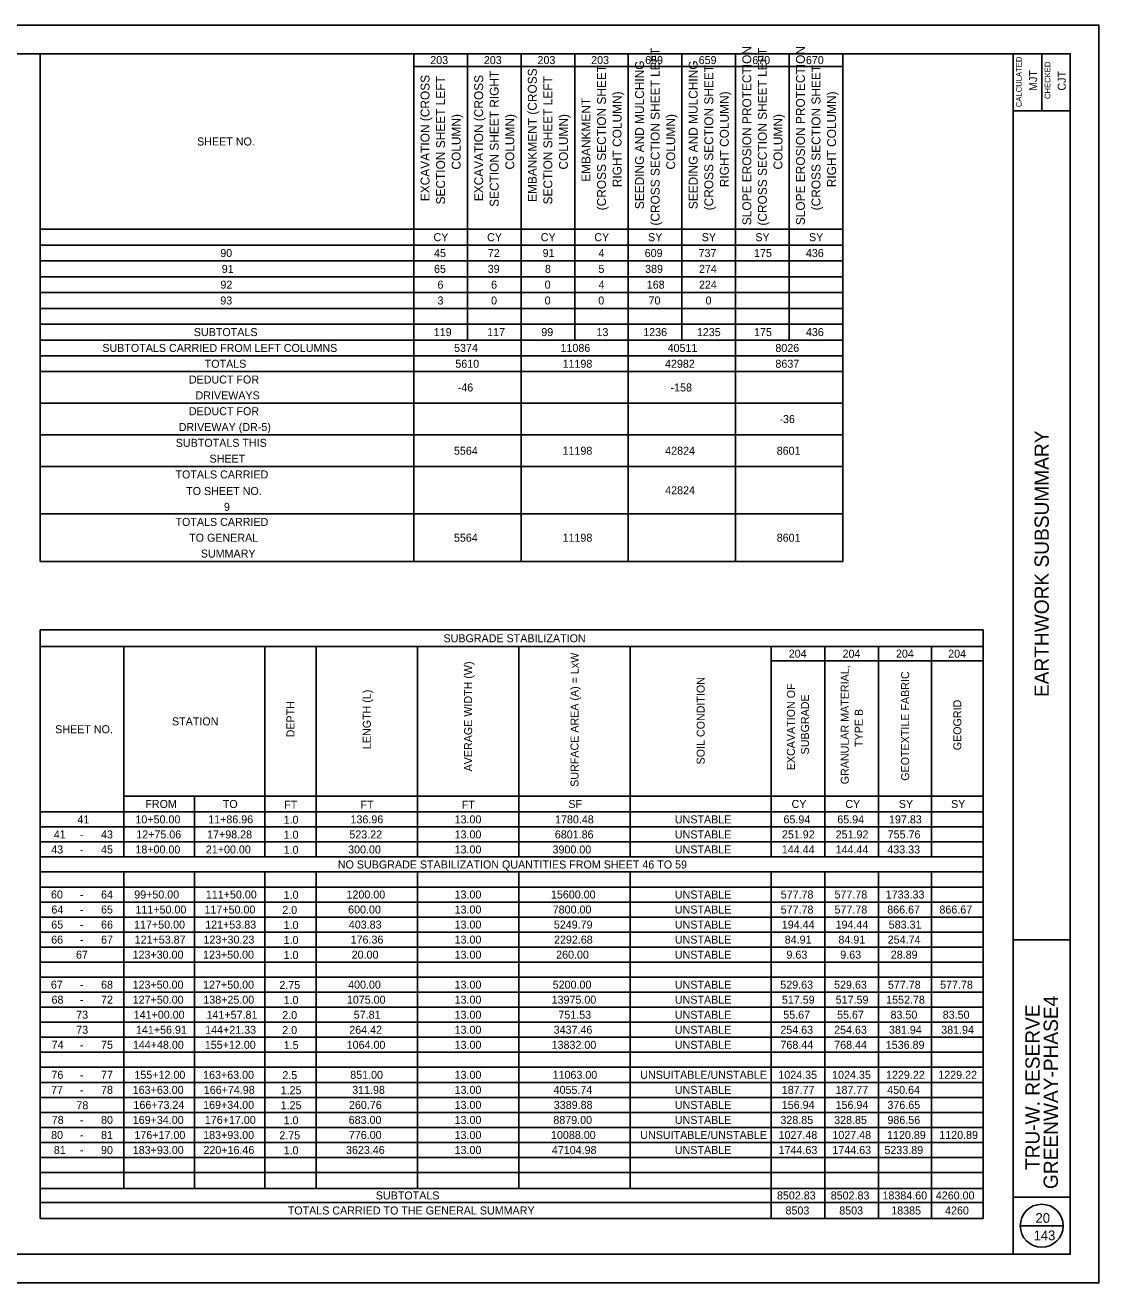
# Model space of a CAD drawing. Extents: x -16 to 102, y -13 to 9.
# Drawn here: x -1.15 to 17.63, y -12.91 to 9.09 of the extents above; entities that cross this region are included whole.
import ezdxf

# ---------------------------------------------------------------- set-up
doc = ezdxf.new("R2010")
doc.units = 0
for name, color, linetype in [('PV_P_EOP', 7, 'Continuous'), ('SH_Border', 7, 'Continuous'), ('SH_Cut_Line', 7, 'Continuous'), ('SH_Data', 7, 'Continuous'), ('TX_P_1', 7, 'Continuous')]:
    doc.layers.add(name, color=color, linetype=linetype)

msp = doc.modelspace()

# ---------------------------------------------------------------- linework, layer by layer
at = {"layer": 'SH_Border'}
for p, q in [((16.129, -12.407), (16.129, 8.593)), ((16.629, 8.593), (16.629, 7.593)), ((16.129, 7.593), (17.129, 7.593)), ((16.129, -6.907), (17.129, -6.907)), ((16.129, -11.407), (17.129, -11.407))]:
    msp.add_line(p, q, dxfattribs=at)
msp.add_lwpolyline([(-14.371, 8.593), (17.129, 8.593), (17.129, -12.407), (-14.371, -12.407)], close=True, dxfattribs=at)
at = {"layer": 'SH_Cut_Line'}
msp.add_lwpolyline([(-16.371, -12.907), (17.629, -12.907), (17.629, 9.093), (-16.371, 9.093)], close=True, dxfattribs=at)
at = {"layer": 'SH_Data'}
for p, q in [((-0.886, 8.593), (13.151, 8.593)), ((-0.886, 8.593), (-0.886, -0.288)), ((5.648, 8.593), (5.648, -0.288)), ((6.586, 8.593), (6.586, 3.585)), ((7.524, 8.593), (7.524, -0.288)), ((8.462, 8.593), (8.462, 3.585)), ((9.4, 8.593), (9.4, -0.288)), ((10.338, 8.593), (10.338, 3.585)), ((11.276, 8.593), (11.276, -0.288)), ((12.214, 8.593), (12.214, 3.585)), ((13.151, 8.593), (13.151, -0.288)), ((5.648, 8.372), (13.151, 8.372)), ((-0.886, 5.522), (13.151, 5.522)), ((-0.886, 5.245), (13.151, 5.245)), ((-0.886, 4.969), (13.151, 4.969)), ((-0.886, 4.692), (13.151, 4.692)), ((-0.886, 4.415), (13.151, 4.415)), ((-0.886, 4.139), (13.151, 4.139)), ((-0.886, 3.862), (13.151, 3.862)), ((-0.886, 3.585), (13.151, 3.585)), ((-0.886, 3.309), (13.151, 3.309)), ((-0.886, 3.032), (13.151, 3.032)), ((-0.886, 2.479), (13.151, 2.479)), ((-0.886, 1.925), (13.151, 1.925)), ((-0.886, 1.372), (13.151, 1.372)), ((-0.886, 0.542), (13.151, 0.542)), ((-0.886, -0.288), (13.151, -0.288)), ((-0.886, -1.487), (15.604, -1.487)), ((-0.886, -1.487), (-0.886, -11.779)), ((15.604, -1.487), (15.604, -11.779)), ((-0.886, -1.777), (15.604, -1.777)), ((0.58, -1.777), (0.58, -5.457)), ((3.043, -1.777), (3.043, -5.457)), ((3.942, -1.777), (3.942, -5.457)), ((5.713, -1.777), (5.713, -5.457)), ((7.483, -1.777), (7.483, -5.457)), ((9.434, -1.777), (9.434, -5.457)), ((11.896, -1.777), (11.896, -5.457)), ((12.837, -1.777), (12.837, -5.457)), ((13.778, -1.777), (13.778, -5.457)), ((14.705, -1.777), (14.705, -5.457)), ((11.896, -2.026), (15.604, -2.026)), ((0.58, -4.392), (15.604, -4.392)), ((1.812, -4.392), (1.812, -5.457)), ((-0.886, -4.669), (15.604, -4.669)), ((-0.886, -4.932), (15.604, -4.932)), ((-0.886, -5.194), (15.604, -5.194)), ((-0.886, -5.457), (15.604, -5.457)), ((-0.886, -5.72), (15.604, -5.72)), ((0.58, -5.72), (0.58, -11.254)), ((1.812, -5.72), (1.812, -11.254)), ((3.043, -5.72), (3.043, -11.254)), ((3.942, -5.72), (3.942, -11.254)), ((5.713, -5.72), (5.713, -11.254)), ((7.483, -5.72), (7.483, -11.254)), ((9.434, -5.72), (9.434, -11.254)), ((11.896, -5.72), (11.896, -11.779)), ((12.837, -5.72), (12.837, -11.779)), ((13.778, -5.72), (13.778, -11.779)), ((14.705, -5.72), (14.705, -11.779)), ((-0.886, -5.983), (15.604, -5.983)), ((-0.886, -6.246), (15.604, -6.246)), ((-0.886, -6.509), (15.604, -6.509)), ((-0.886, -6.771), (15.604, -6.771)), ((-0.886, -7.034), (15.604, -7.034)), ((-0.886, -7.297), (15.604, -7.297)), ((-0.886, -7.56), (15.604, -7.56)), ((-0.886, -7.823), (15.604, -7.823)), ((-0.886, -8.086), (15.604, -8.086)), ((-0.886, -8.348), (15.604, -8.348)), ((-0.886, -8.611), (15.604, -8.611)), ((-0.886, -8.874), (15.604, -8.874)), ((-0.886, -9.137), (15.604, -9.137)), ((-0.886, -9.4), (15.604, -9.4)), ((-0.886, -9.663), (15.604, -9.663)), ((-0.886, -9.926), (15.604, -9.926)), ((-0.886, -10.188), (15.604, -10.188)), ((-0.886, -10.451), (15.604, -10.451)), ((-0.886, -10.714), (15.604, -10.714)), ((-0.886, -10.977), (15.604, -10.977)), ((-0.886, -11.254), (15.604, -11.254)), ((-0.886, -11.503), (15.604, -11.503)), ((-0.886, -11.779), (15.604, -11.779)), ((16.254, -11.907), (17.004, -11.907))]:
    msp.add_line(p, q, dxfattribs=at)
msp.add_circle((16.629, -11.907), 0.375, dxfattribs=at)

# ---------------------------------------------------------------- texts
at = {"layer": 'PV_P_EOP'}
for s, p in [('SHEET NO.', (1.859, 6.988)), ('SUBTOTALS', (1.802, 3.654)), ('SUBTOTALS CARRIED FROM LEFT COLUMNS', (0.202, 3.377)), ('TOTALS', (1.992, 3.1)), ('DEDUCT FOR ', (1.715, 2.824)), ('DRIVEWAYS', (1.831, 2.547)), ('DEDUCT FOR ', (1.715, 2.27)), ('DRIVEWAY (DR-5)', (1.537, 1.994)), ('SUBTOTALS THIS ', (1.486, 1.717)), ('SHEET', (2.077, 1.44)), ('TOTALS CARRIED ', (1.481, 1.164)), (' TO SHEET NO.', (1.616, 0.874)), ('9', (2.328, 0.597)), ('TOTALS CARRIED ', (1.481, 0.333)), (' TO GENERAL ', (1.668, 0.057)), ('SUMMARY', (1.924, -0.22)), ('SUBGRADE STABILIZATION', (6.168, -1.702)), ('STATION', (1.42, -3.155)), ('SHEET NO.', (-0.623, -3.293)), ('FROM', (0.954, -4.6)), ('TO', (2.309, -4.6)), ('SUBTOTALS', (4.984, -11.448)), ('TOTALS CARRIED TO THE GENERAL SUMMARY', (3.444, -11.711))]:
    msp.add_text(s, height=0.14, dxfattribs=at).set_placement(p)
for s, p in [('SURFACE AREA (A) = LxW', (8.529, -4.23)), ('AVERAGE WIDTH (W)', (6.668, -3.961)), ('SOIL CONDITION', (10.735, -3.839)), ('LENGTH (L)', (4.897, -3.57)), ('DEPTH', (3.562, -3.365))]:
    msp.add_text(s, height=0.14, rotation=90, dxfattribs=at).set_placement(p)
at = {"layer": 'SH_Data'}
for s, height, p in [('CALCULATED', 0.1, (16.281, 7.658)), ('CHECKED', 0.1, (16.781, 7.801)), ('MJT', 0.14, (16.549, 7.942)), ('CJT', 0.14, (17.049, 7.949)), ('EARTHWORK SUBSUMMARY', 0.25, (16.754, -2.66)), ('GREENWAY-PHASE4', 0.25, (16.913, -11.266)), ('TRU-W. RESERVE', 0.25, (16.594, -10.934))]:
    msp.add_text(s, height=height, rotation=90, dxfattribs=at).set_placement(p)
for s, p in [('20', (16.521, -11.857)), ('143', (16.488, -12.162))]:
    msp.add_text(s, height=0.17, dxfattribs=at).set_placement(p)
at = {"layer": 'TX_P_1'}
for s, height, p in [('(CROSS SECTION SHEET LEFT', 0.1556, (9.947, 5.587)), ('SLOPE EROSION PROTECTION', 0.1556, (11.55, 5.594)), ('(CROSS SECTION SHEET LEFT', 0.1556, (11.822, 5.587)), ('SLOPE EROSION PROTECTION', 0.1556, (12.488, 5.594)), ('(CROSS SECTION SHEET', 0.1556, (9.009, 5.854)), ('SEEDING AND MULCHING', 0.1556, (9.674, 5.874)), ('SEEDING AND MULCHING', 0.1556, (10.612, 5.874)), ('(CROSS SECTION SHEET', 0.1556, (10.885, 5.854)), ('(CROSS SECTION SHEET', 0.1556, (12.76, 5.854)), ('EXCAVATION (CROSS', 0.1556, (5.923, 6.014)), ('SECTION SHEET LEFT', 0.1556, (6.195, 5.957)), ('EXCAVATION (CROSS', 0.1556, (6.861, 6.014)), ('SECTION SHEET RIGHT', 0.1556, (7.133, 5.914)), ('EMBANKMENT (CROSS', 0.1556, (7.799, 6.001)), ('SECTION SHEET LEFT', 0.1556, (8.071, 5.957)), ('RIGHT COLUMN)', 0.1556, (9.281, 6.258)), ('RIGHT COLUMN)', 0.1556, (11.157, 6.258)), ('RIGHT COLUMN)', 0.1556, (13.033, 6.258)), ('EMBANKMENT', 0.1556, (8.737, 6.353)), ('COLUMN)', 0.1556, (6.467, 6.567)), ('COLUMN)', 0.1556, (7.405, 6.567)), ('COLUMN)', 0.1556, (8.343, 6.567)), ('COLUMN)', 0.1556, (10.219, 6.567)), ('COLUMN)', 0.1556, (12.095, 6.567)), ('GRANULAR MATERIAL,', 0.14, (13.255, -4.186)), ('GEOTEXTILE FABRIC', 0.14, (14.311, -4.124)), ('EXCAVATION OF', 0.14, (12.314, -3.941)), ('SUBGRADE', 0.14, (12.559, -3.664)), ('GEOGRID', 0.14, (15.224, -3.591)), ('TYPE B', 0.14, (13.5, -3.533))]:
    msp.add_text(s, height=height, rotation=90, dxfattribs=at).set_placement(p)
for s, p in [('203', (5.937, 8.412)), ('203', (6.874, 8.412)), ('203', (7.812, 8.412)), ('203', (8.75, 8.412)), ('659', (9.694, 8.412)), ('659', (10.631, 8.412)), ('670', (11.568, 8.412)), ('670', (12.506, 8.412)), ('CY', (5.993, 5.314)), ('CY', (6.931, 5.314)), ('CY', (7.869, 5.314)), ('CY', (8.806, 5.314)), ('SY', (9.746, 5.314)), ('SY', (10.684, 5.314)), ('SY', (11.622, 5.314)), ('SY', (12.56, 5.314)), ('90', (2.264, 5.037)), ('45', (6.003, 5.037)), ('72', (6.943, 5.037)), ('91', (7.902, 5.037)), ('4', (8.879, 5.037)), ('609', (9.687, 5.037)), ('737', (10.629, 5.037)), ('175', (11.599, 5.037)), ('436', (12.506, 5.037)), ('91', (2.29, 4.76)), ('65', (6.002, 4.76)), ('39', (6.941, 4.76)), ('8', (7.942, 4.76)), ('5', (8.878, 4.76)), ('389', (9.694, 4.76)), ('274', (10.636, 4.76)), ('92', (2.267, 4.484)), ('6', (6.063, 4.484)), ('6', (7.001, 4.484)), ('0', (7.937, 4.484)), ('4', (8.879, 4.484)), ('168', (9.723, 4.484)), ('224', (10.636, 4.484)), ('93', (2.265, 4.207)), ('3', (6.063, 4.207)), ('0', (7, 4.207)), ('0', (7.937, 4.207)), ('0', (8.875, 4.207)), ('70', (9.754, 4.207)), ('0', (10.751, 4.207)), ('119', (5.998, 3.654)), ('117', (6.932, 3.654)), ('99', (7.878, 3.654)), ('13', (8.844, 3.654)), ('1236', (9.661, 3.654)), ('1235', (10.599, 3.654)), ('175', (11.599, 3.654)), ('436', (12.506, 3.654)), ('5374', (6.353, 3.377)), ('11086', (8.214, 3.377)), ('40511', (10.087, 3.377)), ('8026', (11.972, 3.377)), ('5610', (6.375, 3.1)), ('11198', (8.25, 3.1)), ('42982', (10.042, 3.1)), ('8637', (11.973, 3.1)), ('-46', (6.417, 2.685)), ('-158', (10.139, 2.685)), ('-36', (12.043, 2.132)), ('5564', (6.351, 1.579)), ('11198', (8.25, 1.579)), ('42824', (10.045, 1.579)), ('8601', (11.995, 1.579)), ('42824', (10.045, 0.887)), ('5564', (6.351, 0.057)), ('11198', (8.25, 0.057)), ('8601', (11.995, 0.057)), ('204', (12.206, -1.971)), ('204', (13.147, -1.971)), ('204', (14.081, -1.971)), ('204', (14.994, -1.971)), ('FT', (3.382, -4.613)), ('FT', (4.717, -4.613)), ('FT', (6.488, -4.613)), ('SF', (8.352, -4.6)), ('CY', (12.255, -4.6)), ('CY', (13.195, -4.6)), ('SY', (14.131, -4.6)), ('SY', (15.044, -4.6)), ('41', (-0.234, -4.87)), ('10+50.00', (0.78, -4.87)), ('11+86.96', (2.053, -4.87)), ('1.0', (3.372, -4.876)), ('136.96', (4.542, -4.87)), ('13.00', (6.362, -4.87)), ('1780.48', (8.119, -4.87)), ('UNSTABLE', (10.214, -4.87)), ('65.94', (12.114, -4.87)), ('65.94', (13.055, -4.87)), ('197.83', (13.959, -4.87)), ('41', (-0.647, -5.133)), ('43', (0.179, -5.133)), ('12+75.06', (0.795, -5.133)), ('17+98.28', (2.034, -5.133)), ('1.0', (3.372, -5.139)), ('523.22', (4.522, -5.133)), ('13.00', (6.362, -5.133)), ('6801.86', (8.115, -5.133)), ('UNSTABLE', (10.214, -5.133)), ('251.92', (12.086, -5.133)), ('251.92', (13.026, -5.133)), ('755.76', (13.936, -5.133)), ('43', (-0.692, -5.396)), ('-', (-0.192, -5.133)), ('45', (0.179, -5.396)), ('18+00.00', (0.78, -5.396)), ('21+00.00', (2.012, -5.396)), ('1.0', (3.372, -5.402)), ('300.00', (4.5, -5.396)), ('13.00', (6.362, -5.396)), ('3900.00', (8.075, -5.396)), ('UNSTABLE', (10.214, -5.396)), ('144.44', (12.085, -5.396)), ('144.44', (13.025, -5.396)), ('433.33', (13.93, -5.396)), ('-', (-0.192, -5.396)), ('NO SUBGRADE STABILIZATION QUANTITIES FROM SHEET 46 TO 59', (4.32, -5.659)), ('60', (-0.696, -6.184)), ('-', (-0.192, -6.184)), ('64', (0.179, -6.184)), ('99+50.00', (0.759, -6.184)), ('111+50.00', (2.012, -6.184)), ('1.0', (3.372, -6.19)), ('1200.00', (4.472, -6.184)), ('13.00', (6.362, -6.184)), ('15600.00', (8.047, -6.184)), ('UNSTABLE', (10.214, -6.184)), ('577.78', (12.065, -6.184)), ('577.78', (13.006, -6.184)), ('1733.33', (13.902, -6.184)), ('64', (-0.689, -6.447)), ('65', (0.179, -6.447)), ('111+50.00', (0.781, -6.447)), ('117+50.00', (1.988, -6.447)), ('2.0', (3.348, -6.453)), ('600.00', (4.5, -6.447)), ('13.00', (6.362, -6.447)), ('7800.00', (8.078, -6.447)), ('UNSTABLE', (10.214, -6.447)), ('577.78', (12.065, -6.447)), ('577.78', (13.006, -6.447)), ('866.67', (13.928, -6.447)), ('866.67', (14.841, -6.447)), ('65', (-0.692, -6.71)), ('-', (-0.192, -6.447)), ('66', (0.179, -6.71)), ('117+50.00', (0.757, -6.71)), ('121+53.83', (2.001, -6.71)), ('1.0', (3.372, -6.716)), ('403.83', (4.512, -6.71)), ('13.00', (6.362, -6.71)), ('5249.79', (8.098, -6.71)), ('UNSTABLE', (10.214, -6.71)), ('194.44', (12.084, -6.71)), ('194.44', (13.025, -6.71)), ('583.31', (13.954, -6.71)), ('-', (-0.192, -6.71)), ('66', (-0.693, -6.973)), ('-', (-0.192, -6.973)), ('67', (0.179, -6.973)), ('121+53.87', (0.767, -6.973)), ('123+30.23', (1.97, -6.973)), ('1.0', (3.372, -6.979)), ('176.36', (4.544, -6.973)), ('13.00', (6.362, -6.973)), ('2292.68', (8.101, -6.973)), ('UNSTABLE', (10.214, -6.973)), ('84.91', (12.135, -6.973)), ('84.91', (13.075, -6.973)), ('254.74', (13.937, -6.973)), ('67', (-0.259, -7.236)), ('123+30.00', (0.73, -7.236)), ('123+50.00', (1.963, -7.236)), ('1.0', (3.372, -7.242)), ('20.00', (4.562, -7.236)), ('13.00', (6.362, -7.236)), ('260.00', (8.138, -7.236)), ('UNSTABLE', (10.214, -7.236)), ('9.63', (12.166, -7.236)), ('9.63', (13.107, -7.236)), ('28.89', (13.99, -7.236)), ('67', (-0.698, -7.761)), ('-', (-0.192, -7.761)), ('68', (0.179, -7.761)), ('123+50.00', (0.731, -7.761)), ('127+50.00', (1.964, -7.761)), ('2.75', (3.297, -7.767)), ('400.00', (4.5, -7.761)), ('13.00', (6.362, -7.761)), ('5200.00', (8.078, -7.761)), ('UNSTABLE', (10.214, -7.761)), ('529.63', (12.058, -7.761)), ('529.63', (12.999, -7.761)), ('577.78', (13.94, -7.761)), ('577.78', (14.853, -7.761)), ('68', (-0.687, -8.024)), ('72', (0.179, -8.024)), ('127+50.00', (0.733, -8.024)), ('138+25.00', (1.968, -8.024)), ('1.0', (3.372, -8.03)), ('1075.00', (4.478, -8.024)), ('13.00', (6.362, -8.024)), ('13975.00', (8.059, -8.024)), ('UNSTABLE', (10.214, -8.024)), ('517.59', (12.086, -8.024)), ('517.59', (13.027, -8.024)), ('1552.78', (13.909, -8.024)), ('-', (-0.192, -8.024)), ('73', (-0.255, -8.287)), ('141+00.00', (0.75, -8.287)), ('141+57.81', (2.024, -8.287)), ('2.0', (3.348, -8.293)), ('57.81', (4.598, -8.287)), ('13.00', (6.362, -8.287)), ('751.53', (8.177, -8.287)), ('UNSTABLE', (10.214, -8.287)), ('55.67', (12.11, -8.287)), ('55.67', (13.051, -8.287)), ('83.50', (13.986, -8.287)), ('83.50', (14.899, -8.287)), ('73', (-0.255, -8.55)), ('141+56.91', (0.789, -8.55)), ('144+21.33', (2, -8.55)), ('2.0', (3.348, -8.556)), ('264.42', (4.52, -8.55)), ('13.00', (6.362, -8.55)), ('3437.46', (8.095, -8.55)), ('UNSTABLE', (10.214, -8.55)), ('254.63', (12.059, -8.55)), ('254.63', (12.999, -8.55)), ('381.94', (13.959, -8.55)), ('381.94', (14.872, -8.55)), ('74', (-0.685, -8.813)), ('-', (-0.192, -8.813)), ('75', (0.179, -8.813)), ('144+48.00', (0.736, -8.813)), ('155+12.00', (1.994, -8.813)), ('1.5', (3.374, -8.819)), ('1064.00', (4.475, -8.813)), ('13.00', (6.362, -8.813)), ('13832.00', (8.059, -8.813)), ('UNSTABLE', (10.214, -8.813)), ('768.44', (12.061, -8.813)), ('768.44', (13.001, -8.813)), ('1536.89', (13.903, -8.813)), ('76', (-0.689, -9.338)), ('77', (0.179, -9.338)), ('155+12.00', (0.763, -9.338)), ('163+63.00', (1.964, -9.338)), ('2.5', (3.35, -9.344)), ('851.00', (4.537, -9.338)), ('13.00', (6.362, -9.338)), ('11063.00', (8.076, -9.338)), ('UNSUITABLE/UNSTABLE', (9.609, -9.338)), ('1024.35', (12.024, -9.338)), ('1024.35', (12.964, -9.338)), ('1229.22', (13.907, -9.338)), ('1229.22', (14.821, -9.338)), ('-', (-0.192, -9.338)), ('78', (0.179, -9.601)), ('163+63.00', (0.733, -9.601)), ('166+74.98', (1.976, -9.601)), ('311.98', (4.571, -9.601)), ('13.00', (6.362, -9.601)), ('4055.74', (8.093, -9.601)), ('UNSTABLE', (10.214, -9.601)), ('187.77', (12.084, -9.601)), ('187.77', (13.024, -9.601)), ('450.64', (13.928, -9.601)), ('77', (-0.694, -9.601)), ('-', (-0.192, -9.601)), ('1.25', (3.32, -9.607)), ('78', (-0.252, -9.87)), ('166+73.24', (0.746, -9.864)), ('169+34.00', (1.965, -9.864)), ('1.25', (3.32, -9.87)), ('260.76', (4.515, -9.864)), ('13.00', (6.362, -9.864)), ('3389.88', (8.097, -9.864)), ('UNSTABLE', (10.214, -9.864)), ('156.94', (12.084, -9.864)), ('156.94', (13.025, -9.864)), ('376.65', (13.932, -9.864)), ('78', (-0.683, -10.127)), ('-', (-0.192, -10.127)), ('80', (0.179, -10.127)), ('169+34.00', (0.734, -10.127)), ('176+17.00', (1.994, -10.127)), ('1.0', (3.372, -10.133)), ('683.00', (4.51, -10.127)), ('13.00', (6.362, -10.127)), ('8879.00', (8.089, -10.127)), ('UNSTABLE', (10.214, -10.127)), ('328.85', (12.06, -10.127)), ('328.85', (13, -10.127)), ('986.56', (13.932, -10.127)), ('80', (-0.694, -10.39)), ('-', (-0.192, -10.39)), ('81', (0.179, -10.39)), ('176+17.00', (0.763, -10.39)), ('183+93.00', (1.965, -10.39)), ('2.75', (3.297, -10.396)), ('776.00', (4.513, -10.39)), ('13.00', (6.362, -10.39)), ('10088.00', (8.048, -10.39)), ('UNSUITABLE/UNSTABLE', (9.609, -10.39)), ('1027.48', (12.028, -10.39)), ('1027.48', (12.969, -10.39)), ('1120.89', (13.925, -10.39)), ('1120.89', (14.838, -10.39)), ('81', (-0.646, -10.653)), ('90', (0.179, -10.653)), ('183+93.00', (0.734, -10.653)), ('220+16.46', (1.97, -10.653)), ('1.0', (3.372, -10.659)), ('3623.46', (4.463, -10.653)), ('13.00', (6.362, -10.653)), ('47104.98', (8.063, -10.653)), ('UNSTABLE', (10.214, -10.653)), ('1744.63', (12.029, -10.653)), ('1744.63', (12.969, -10.653)), ('5233.89', (13.879, -10.653)), ('-', (-0.192, -10.653)), ('8502.83', (12, -11.448)), ('8502.83', (12.94, -11.448)), ('18384.60', (13.845, -11.448)), ('4260.00', (14.778, -11.448)), ('8503', (12.149, -11.711)), ('8503', (13.089, -11.711)), ('18385', (13.999, -11.711)), ('4260', (14.94, -11.711))]:
    msp.add_text(s, height=0.14, dxfattribs=at).set_placement(p)

doc.saveas('drawing.dxf')
